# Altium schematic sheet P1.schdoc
size 297 x 209 mm; Symbol: Drawing-Symbol_A4; Company: 嘉立创EDA; Version: V1.0; Page Size: A4; @Project Name: mairui N1; @Update Date: 2026-05-08; @Create Date: 2026-05-08; Device: Drawing-Symbol_A4; @Board Name: 顶板_2; @Page Name: P1; @Create Time: 14:05:01; @Page Count: 3; @Page No: 3; @Schematic Name: Top_2; @Update Time: 14:05:01; @Assembly Variant: Basic; Border: 1; Title Block Position: 3; Size: A4; Width: 1170; Height: 825; Region Start: 1; X Region Count: 6; Y Region Count: 4; Blade Width: 10
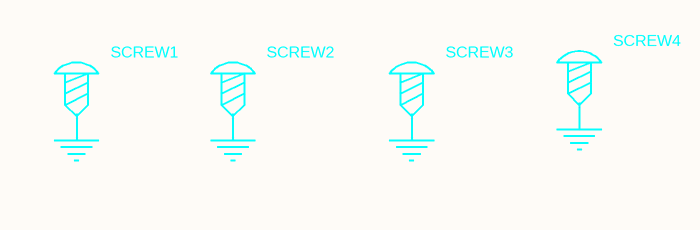
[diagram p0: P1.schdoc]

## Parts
SCREW1  (no value)  [M3螺丝]
SCREW2  (no value)  [M3螺丝]
SCREW3  (no value)  [M3螺丝]
SCREW4  (no value)  [M3螺丝]

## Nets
GND: SCREW1.1 SCREW2.1 SCREW3.1 SCREW4.1

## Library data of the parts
SCREW1-SCREW4 = M3螺丝: Symbol: 螺丝孔; ConvertToPcb: yes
